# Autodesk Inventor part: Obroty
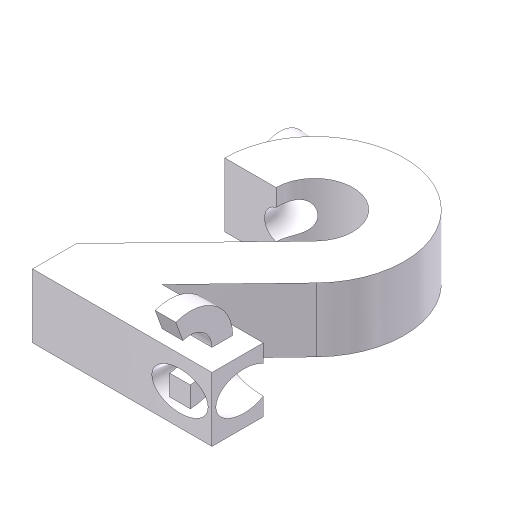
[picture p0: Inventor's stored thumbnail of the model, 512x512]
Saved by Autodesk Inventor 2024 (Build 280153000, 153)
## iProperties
Company: ATC
Created: 2023-03
Part Number: Obroty
Document SubType Name: Modeling
Designer: Andrzej Jaskulski
Density: 1 g/cm^3
Material: Kurs-AJ
Appearance: Kurs-AJ
Checked By: A.J.
Engr Approved By: Andrzej Jaskulski
Mfg Approved By: Andrzej Jaskulski
Authority: A.J.
Title: A.J.: Kurs R2024-MEP
Author: Andrzej Jaskulski
Revision Number: 1/24
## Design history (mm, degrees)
sketch "Zarys dwójki"
  geometry: L1 (0, 0)-(140, 0); L2 (140, 0)-(140, 40); L3 (140, 40)-(61.086, 40); L4 (0, 0)-(0, 34.326); L5 (0, 34.326)-(91.58, 129.16); L6 (61.086, 40)-(120.354, 101.374); L7 (40, 150)-(0, 150); A1 r 30 centre (70, 150) between (91.58, 129.16) and (40, 150); A2 r 70 centre (70, 150) between (120.354, 101.374) and (0, 150)
  constraints: 14 end point, 4 point on circle, 3 perpendicular, 2 centre point, 2 parallel, 2 tangent, 1 coincident, 1 horizontal, 1 point on line, 1 other
  dimensions: "d0" = 140 distance of L1.start L1.end; "d1" = 150 distance from line of A1.centre L1; "d2" = 70 radius of A2; "d3" = 30 radius of A1; "d4" = 70 distance from line of L4 A1.centre; "d5" = 46 deg angle of L6 L3; "d6" = 40 distance of L1.end L2.end
extrude "Dwójka" new body sketch "Zarys dwójki" distance "d7" = 50; taper "d8" = 0 deg
node "Odsunięta od Stycznej do Walca"
  node "Styczna do Walca"
node "Oś powierzchni walcowej"
sketch "Elipsa i Kwadrat"
  geometry: L1 (140, 0)-(140, 50) reference; L2 (106.938, 16.938)-(123.062, 16.938); L3 (123.062, 16.938)-(123.062, 33.062); L4 (123.062, 33.062)-(106.938, 33.062); L5 (106.938, 33.062)-(106.938, 16.938); L6 (140, 50)-(0, 50) reference; L7 (0, 0)-(0, 50) reference; L8 (0, 0)-(140, 0) reference; 4 further points; 1 other entity
  constraints: 8 end point, 3 midpoint, 2 horizontal alignment, 2 parallel, 2 perpendicular, 1 horizontal, 1 vertical alignment, 2 other
sketch "Okręgi"
  geometry: L1 (0, 150)-(50, 150) reference; C1 r 12 at (25, 193); C2 r 21.5 at (25, 193); 1 further point
  constraints: 2 centre point, 1 coincident, 1 midpoint, 1 vertical alignment
revolve "Obrót o kąt 1" stored, may be unused: angle "d18" = 30 deg
revolve "Obrót do następnego" stored, may be unused: angle "d19" = 30 deg
revolve "Obrót pełny w podstawie" stored, may be unused: angle "d21" = 200 deg
revolve "Obrót o kąt w podstawie" stored, may be unused: angle "d20" = 200 deg
node "Bryła1"
node "Korpusy bryłowe"
node "Korpusy powierzchniowe"
